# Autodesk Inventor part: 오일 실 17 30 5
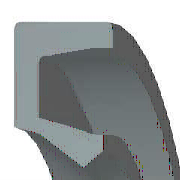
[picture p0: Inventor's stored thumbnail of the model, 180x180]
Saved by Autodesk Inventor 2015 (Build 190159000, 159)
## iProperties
IsCustomPart: 1
Created: 2012-02
Part Number: 오일 실 17 30 5
Material: 고무
Description: 오일 실 - 비스프링, 금속 케이스 GM
Document SubType Name: Modeling
Standard: JIS B 2402
Designer: mduedu
Standards Organization: JIS
Language: ko-KR
Size Designation: 17 30 5 B
Categories: <MemberInstance><Categories><Category DisplayName="샤프트 부품" InternalName="7f7aeb1f-a693-4053-b835-cee3144e0d98" Mnemonic="SHFT"><Category DisplayName="실링" Intern
Density: 0.93 g/cm^3
Appearance: Rubber-Black
Author: mduedu
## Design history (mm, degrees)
body "Solid1"
revolve "회전1" stored, may be unused: angle "d27" = 360 deg
fillet "모깎기1" dims "d28" = 0.25 (= 0.05 x b)
chamfer "모따기1" distance "d29" = 0.07143 (= 0.0142857 x b); stored, may be unused: second distance "d30" = 0.25 (= 0.05 x b), angle "d35" = 45 deg
sketch "스케치2"
  geometry: L1 (-9.367, -3.238)-(-10.233, -3.863); L2 (-8.5, -1.625)-(-9.367, -3.238); L3 (-9.15, -1)-(-8.5, -1.625); L4 (-11.317, -3.75)-(-9.15, -1); L5 (-13.075, -3.75)-(-11.317, -3.75); L6 (-14.375, -1.25)-(-13.075, -3.75); L7 (-14.375, 0)-(-14.375, -1.25); L8 (-15, 0)-(-14.375, 0); L9 (-15, -5)-(-15, 0); L10 (-11.129, -5)-(-15, -5); L11 (-10.233, -3.863)-(-11.129, -5); L12 (0, -9.6)-(0, 1.6) reference; L13 (-14, 0)-(-28, 0) reference
  constraints: 22 end point, 3 horizontal, 2 vertical, 1 parallel
  dimensions: "d2" = 5 distance of L9.start L8.start (= b); "d4" = 1 vertical distance of L8.start L3.start (= 0.2 x b); "d6" = 0.625 distance of L8.start L7.start (= 0.125 x b); "d8" = 1.25 distance of L7.start L6.start (= 0.25 x b); "d10" = 1.25 vertical distance of L5.start L9.start (= 0.25 x b); "d12" = 1.3 horizontal distance of L6.start L5.start (= 0.1 x dd - 0.1 x Diam); "d14" = 1.6129 vertical distance of L2.start L1.start (= 0.322581 x b); "d16" = 0.86667 horizontal distance of L1.start L1.end (= 0.0666667 x dd - 0.0666667 x Diam); "d18" = 0.86667 horizontal distance of L2.start L1.start (= 0.0666667 x dd - 0.0666667 x Diam); "d20" = 0.625 vertical distance of L3.start L2.start (= 0.125 x b); "d22" = 0.65 horizontal distance of L3.start L2.start (= 0.05 x dd - 0.05 x Diam); "d24" = 0.625 vertical distance of L1.start L1.end (= 0.125 x b); "d26" = 2.16667 horizontal distance of L4.start L3.start (= 0.166667 x dd - 0.166667 x Diam); "d31" = 0 distance between parallel lines of L8 L13; "d32" = 15 distance between parallel lines of L12 L9 (= 0.5 x dd); "d33" = 8.5 distance from line of L12 L2.start (= 0.5 x Diam)
other parameters: "Diam" = 17 [user parameter; used in 6 equation terms], "b" = 5 [user parameter; used in 11 equation terms], "d1" = 8 (derived), "d3" = 1.6 (derived), "d5" = 1 (derived), "d7" = 2 (derived), "d9" = 2 (derived), "d11" = 2 (derived), "d13" = 2.58065 (derived), "d15" = 1.33333 (derived), "d17" = 1.33333 (derived), "d19" = 1 (derived), "d21" = 1 (derived), "d23" = 1 (derived), "d25" = 3.33333 (derived), "d34" = 0
